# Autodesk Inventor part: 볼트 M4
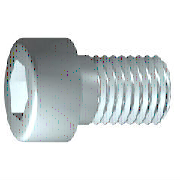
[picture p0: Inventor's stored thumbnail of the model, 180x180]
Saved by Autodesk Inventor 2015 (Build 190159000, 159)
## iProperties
IsCustomPart: 1
Created: 2015-10
Part Number: 볼트 M4
Material: 스테인리스강
Description: 6각머리 태핑 나사
Document SubType Name: Modeling
Standard: KS B 1003
Designer: mdu
Standards Organization: KS
Language: ko-KR
Size Designation: M 4 x 16
Categories: <MemberInstance><Categories><Category DisplayName="조임쇠" InternalName="e4da775c-781d-43d5-af7c-5136215cf5a6" Mnemonic="FSTN"><Category DisplayName="볼트" InternalN
Density: 8.08 g/cm^3
Mass: 2.70334 g
Surface Area: 3.81118 cm^2
Volume: 0.334572 cm^3
Appearance: 반광택
Author: mdu
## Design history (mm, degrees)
sketch "스케치1"
  geometry: L1 (-1, 0)-(16, 0); L2 (16, 0)-(16, 2); L3 (16, 2)-(1.75, 2); L4 (1.75, 2)-(1.32, 2); L5 (1.32, 2)-(0, 2); L6 (0, 2)-(0, 3.5); L7 (0, 3.5)-(-4, 3.5); L8 (-4, 3.5)-(-4, 1.732); L9 (-4, 1.732)-(-2, 1.732); L10 (-2, 1.732)-(-1, 0); L11 (-8, 0)-(20, 0) reference; L12 (0, -0.7)-(0, 4.2) reference; L13 (1.75, 2)-(0, 2)
  constraints: 22 end point, 6 parallel, 2 collinear, 2 perpendicular, 1 horizontal, 1 point on line
  dimensions: "d1" = 14.25 distance from line of L3.end L2 (= GEL); "d2" = 0.42952 distance of L4.end L3.end (computed from GAL); "d3" = 4 distance between parallel lines of L8 L6 (= KOH); "d4" = 2 distance of L8.end L9.end (= INTI); "d5" = 60 deg angle of L10 L1; "d6" = 4 diameter of L3 L1 (= GD); "d7" = 4 diameter of L5 L1 (= BDM); "d8" = 3.4641 diameter of L9 L1 (= 1.1547 x SW); "d9" = 7 diameter of L7 L1 (= KOD); "d26" = 16 distance between parallel lines of L12 L2 (= NLG)
revolve "본체" sketch "스케치1" stored, may be unused: angle "d10" = 90 deg
sketch "스케치2"
  geometry: L1 (0, -4.9)-(0, 4.9) reference; L2 (-4.9, 0)-(4.9, 0) reference; L3 (1.732, 0)-(0.866, -1.5); L4 (0.866, -1.5)-(-0.866, -1.5); L5 (-0.866, -1.5)-(-1.732, 0); L6 (-1.732, 0)-(-0.866, 1.5); L7 (-0.866, 1.5)-(0.866, 1.5); L8 (0.866, 1.5)-(1.732, 0); 2 further points
  constraints: 12 end point, 1 coincident, 1 horizontal alignment, 1 point on line, 12 other
extrude "슬롯" join sketch "스케치2" stored distance "d11" = 10; taper "d12" = 0 deg
workplane "Work Plane1"
fillet "Fillet2" dims "d30" = 0.1 (= R)
body "Solid1"
fillet "모깎기1" dims "d17" = 0.4 (= RR)
feature "스레드" dims "d13" = 14.25 (= GEL), "d14" = 0
chamfer "모따기1" distance "d15" = 0.42941 (= -0.5 x SPD + 0.5 x GD); stored, may be unused: second distance "d16" = 0.42941 (= GUL), angle "d27" = 45 deg
other parameters: "GD" = 4 (= NND) [user parameter; used in 2 equation terms], "NLG" = 16 [user parameter; used in 1 equation term], "GEL" = 14.25 [user parameter; used in 2 equation terms], "KOD" = 7 [user parameter; used in 1 equation term], "KOH" = 4 [user parameter; used in 1 equation term], "INTI" = 2 [user parameter; used in 1 equation term], "GAL" = 0.42941 (= 0.61345 x PTC) [user parameter; used in 1 equation term], "GUL" = 0.42941 (= 0.61345 x PTC) [user parameter; used in 1 equation term], "BDM" = 4 (= NND) [user parameter; used in 1 equation term], "SW" = 3 [user parameter; used in 2 equation terms], "RR" = 0.4 [user parameter; used in 1 equation term], "SPD" = 3.14117 (= NND - 1.2269 x PTC) [user parameter; used in 1 equation term], "d19" = 0, "d28" = 0, "d29" = 0, "R" = 0.1 [user parameter; used in 1 equation term], "PHH" = 0.2 [user parameter], "GD1" = 3.14117 (= THREADDIA - 1.2269 x PTC) [user parameter], "THREADDIA" = 4 [user parameter; used in 1 equation term], "FAWI" = 45 deg [user parameter], "TPU" = 14.28571 (computed from PTC) [user parameter], "PTC" = 0.7 [user parameter; used in 5 equation terms], "NND" = 4 [user parameter; used in 3 equation terms], "TOA" = 30 deg [user parameter], "E0" = 3.465 (= 1.155 x SW) [user parameter]
